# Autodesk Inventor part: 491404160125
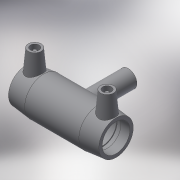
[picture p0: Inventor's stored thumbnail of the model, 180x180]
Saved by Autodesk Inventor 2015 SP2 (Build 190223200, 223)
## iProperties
Created: 2017-06
Part Number: 491404160125
Material: Generic
Description: PLASSON REDUCING TEE 160x125x160
Document SubType Name: Modeling
Designer: KIM
Mass: 57.3761 g
Surface Area: 241.06 cm^2
Volume: 57.3761 cm^3
Density: 1 g/cm^3
Appearance: Default
Author: KIM
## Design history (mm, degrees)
derived "491404.ipt"
feature "Solid1::491404.ipt"
tag "TaggingFeature1"
body "Solid1"
other parameters: "d2" = 208, "d3" = 86, "d4" = 88, "d5" = 187.2, "d6" = 152, "d8" = 168 deg, "d10" = 34.4, "d11" = 11.46667, "d14" = 17.6296, "d17" = 144, "d19" = 3.52592, "d20" = 168 deg, "d22" = 193.44, "d23" = 208, "d25" = 135 deg, "d26" = 308, "d29" = 106, "d30" = 15, "d31" = 176, "d34" = 5 deg, "d35" = 15, "d39" = 5 deg, "d41" = 4, "d42" = 14, "d43" = 0, "d45" = 4, "d46" = 6, "d47" = 0, "d48" = -198, "d49" = 125, "d51" = 0, "d54" = 0, "d55" = 187.2, "d56" = 208, "d57" = 154, "d58" = 135 deg, "d59" = 86, "d60" = 86, "d61" = 135 deg, "d62" = 198, "d72" = 200.2, "d73" = 100.1, "d74" = -198, "d75" = 131.25, "d77" = 0, "d80" = 0, "d81" = 125, "d82" = 94, "d83" = 0, "d84" = 3, "d85" = 0, "d86" = 28.66667, "d87" = 189.5712, "d88" = 11.46667, "d89" = 3, "d90" = 0, "L_1" = 86, "D_" = 208, "A_" = 106, "d_2" = 12, "H_" = 198, "d_1" = 125
